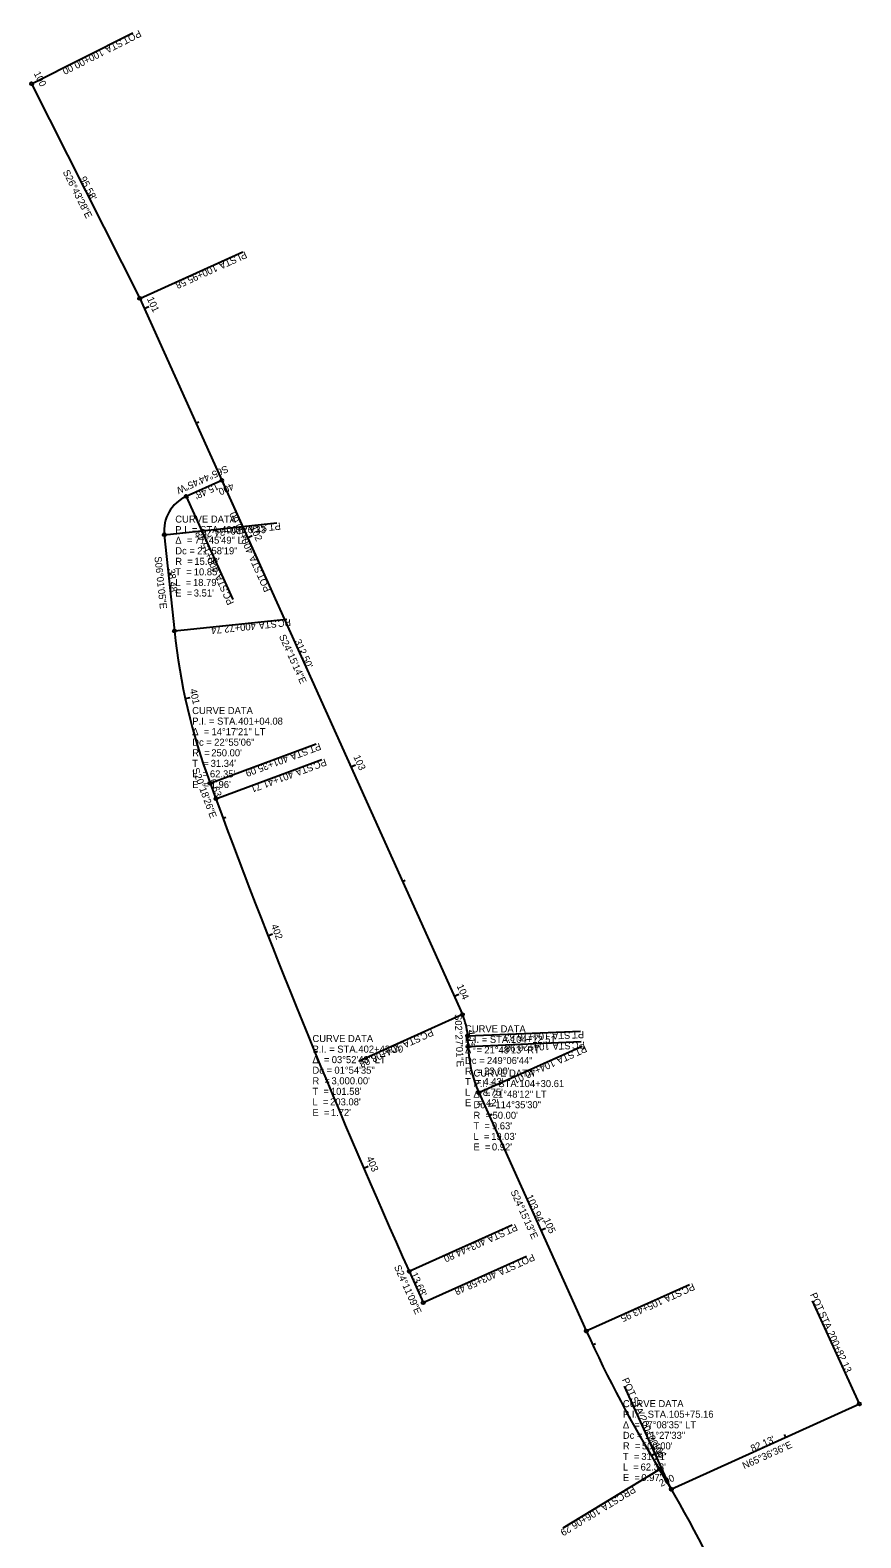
# Model space of a CAD drawing. Extents: x 1584180 to 1585753, y 271314 to 274821.
# Drawn here: x 1584180 to 1584511, y 274221 to 274821 of the extents above; entities that cross this region are included whole.
import ezdxf

# ---------------------------------------------------------------- set-up
doc = ezdxf.new("R2010")
doc.units = 0
for name, color, linetype in [('GE_P_Alignment', 7, 'Continuous'), ('GE_P_Alignment_100_Bearings', 7, 'Continuous'), ('GE_P_Alignment_100_Cardinal_Points', 7, 'Continuous'), ('GE_P_Alignment_100_Curve_Data', 7, 'Continuous'), ('GE_P_Alignment_100_Distances', 7, 'Continuous'), ('GE_P_Alignment_100_Stations', 7, 'Continuous')]:
    doc.layers.add(name, color=color, linetype=linetype)

msp = doc.modelspace()

# ---------------------------------------------------------------- linework, layer by layer
at = {"layer": 'GE_P_Alignment'}
for p, q in [((1584180.89, 274799.28), (1584223.87, 274713.91)), ((1584180.89, 274799.28), (1584223.87, 274713.91)), ((1584223.87, 274713.91), (1584352.24, 274429)), ((1584223.87, 274713.91), (1584352.24, 274429)), ((1584256.5, 274641.5), (1584242.39, 274635.14)), ((1584233.63, 274619.9), (1584237.66, 274581.63)), ((1584251.83, 274521.08), (1584254.13, 274514.86)), ((1584354.25, 274420.53), (1584354.43, 274416.38)), ((1584358.8, 274397.98), (1584401.49, 274303.22)), ((1584331, 274326.93), (1584336.6, 274314.45)), ((1584435.28, 274240.25), (1584510.08, 274274.17))]:
    msp.add_line(p, q, dxfattribs=at)
for centre, radius, start, end in [((1584248.55, 274621.47), 15, 114.25424, 186.01792), ((1584486.29, 274607.84), 250, 186.01792, 200.30709), ((1587067.66, 275556.02), 3000, 200.30709, 204.1857), ((1584331.27, 274419.55), 23, 2.45028, 24.25402), ((1584404.38, 274418.52), 50, 182.45028, 204.25365), ((1584857.36, 274508.6), 500, 204.25365, 211.39671), ((1584003.78, 273987.64), 500, 24.10913, 31.39671)]:
    msp.add_arc(centre, radius, start, end, dxfattribs=at)
at = {"layer": 'GE_P_Alignment_100_Cardinal_Points'}
for p, q in [((1584180.89, 274799.28), (1584221.08, 274819.52)), ((1584223.87, 274713.91), (1584264.9, 274732.4)), ((1584256.5, 274641.5), (1584274.98, 274600.47)), ((1584242.39, 274635.14), (1584260.87, 274594.12)), ((1584233.63, 274619.9), (1584278.38, 274624.61)), ((1584237.66, 274581.63), (1584282.42, 274586.35)), ((1584251.83, 274521.08), (1584294.03, 274536.7)), ((1584254.13, 274514.86), (1584296.33, 274530.48)), ((1584352.24, 274429), (1584311.21, 274410.51)), ((1584354.25, 274420.53), (1584399.21, 274422.46)), ((1584354.43, 274416.38), (1584399.39, 274418.31)), ((1584358.8, 274397.98), (1584399.82, 274416.47)), ((1584331, 274326.93), (1584372.05, 274345.37)), ((1584336.6, 274314.45), (1584377.65, 274332.89)), ((1584401.49, 274303.22), (1584442.52, 274321.7)), ((1584510.08, 274274.17), (1584491.5, 274315.15)), ((1584435.28, 274240.25), (1584416.69, 274281.24)), ((1584430.57, 274248.12), (1584392.16, 274224.68))]:
    msp.add_line(p, q, dxfattribs=at)
for centre in [(1584180.89, 274799.28), (1584223.87, 274713.91), (1584256.5, 274641.5), (1584242.39, 274635.14), (1584233.63, 274619.9), (1584237.66, 274581.63), (1584251.83, 274521.08), (1584254.13, 274514.86), (1584352.24, 274429), (1584354.25, 274420.53), (1584354.43, 274416.38), (1584358.8, 274397.98), (1584331, 274326.93), (1584336.6, 274314.45), (1584401.49, 274303.22), (1584510.08, 274274.17), (1584430.57, 274248.12), (1584435.28, 274240.25)]:
    msp.add_circle(centre, 0.6, dxfattribs=at)
at = {"layer": 'GE_P_Alignment_100_Stations'}
for p, q in [((1584180.89, 274799.28), (1584182.68, 274800.18)), ((1584203.37, 274754.62), (1584204.45, 274755.16)), ((1584225.69, 274709.88), (1584227.51, 274710.7)), ((1584246.23, 274664.3), (1584247.32, 274664.79)), ((1584256.5, 274641.5), (1584257.32, 274639.68)), ((1584266.77, 274618.71), (1584268.59, 274619.53)), ((1584235.28, 274604.25), (1584236.47, 274604.37)), ((1584287.31, 274573.12), (1584288.4, 274573.62)), ((1584241.99, 274554.73), (1584243.95, 274555.16)), ((1584307.84, 274527.54), (1584309.67, 274528.36)), ((1584257.01, 274507.1), (1584258.14, 274507.52)), ((1584328.38, 274481.95), (1584329.48, 274482.44)), ((1584274.88, 274460.4), (1584276.74, 274461.13)), ((1584348.92, 274436.36), (1584350.75, 274437.18)), ((1584293.53, 274414.01), (1584294.64, 274414.47)), ((1584362.9, 274388.87), (1584363.99, 274389.37)), ((1584312.95, 274367.94), (1584314.78, 274368.73)), ((1584383.44, 274343.29), (1584385.26, 274344.11)), ((1584333.13, 274322.19), (1584334.22, 274322.68)), ((1584404.01, 274297.72), (1584405.1, 274298.22)), ((1584480.81, 274260.9), (1584480.32, 274261.99)), ((1584427.33, 274253.51), (1584429.05, 274254.53)), ((1584435.28, 274240.25), (1584434.45, 274242.07))]:
    msp.add_line(p, q, dxfattribs=at)

# ---------------------------------------------------------------- texts
at = {"layer": 'GE_P_Alignment_100_Bearings'}
for s, rotation, p in [('S26°43\'28"E', 296.72445, (1584193.17, 274764.21)), ('S65°44\'45"W', 204.25424, (1584258.31, 274647.58)), ('S06°01\'05"E', 276.01792, (1584229.73, 274611.14)), ('S24°15\'14"E', 294.25402, (1584279.19, 274579.46)), ('S20°18\'26"E', 290.30709, (1584244.68, 274526.56)), ('S02°27\'01"E', 272.45028, (1584349.08, 274429.18)), ('S24°15\'13"E', 294.25365, (1584371.27, 274358.6)), ('S24°11\'09"E', 294.1857, (1584324.94, 274328.7)), ('N65°36\'36"E', 24.39003, (1584464.31, 274248.15))]:
    msp.add_text(s, height=2.8, rotation=rotation, dxfattribs=at).set_placement(p)
at = {"layer": 'GE_P_Alignment_100_Cardinal_Points'}
for s, rotation, p in [('POT', 206.72445, (1584223.6, 274820.74)), ('100+00.00', 206.72445, (1584208.73, 274813.25)), (' STA. ', 206.72445, (1584217.17, 274817.5)), (' STA. ', 204.25402, (1584262.63, 274731.33)), ('PI', 204.25402, (1584265.72, 274732.72)), ('100+95.58', 204.25402, (1584254.01, 274727.45)), ('400+00.00', 114.25424, (1584269.25, 274613.09)), ('400+15.48', 114.25424, (1584255.67, 274605.55)), ('400+34.26', 186.01792, (1584266.01, 274623.27)), (' STA. ', 186.01792, (1584275.41, 274624.26)), ('PT', 186.01792, (1584279.8, 274624.72)), (' STA. ', 114.25424, (1584273.14, 274604.47)), (' STA. ', 114.25424, (1584259.56, 274596.93)), ('POT', 114.25424, (1584276.09, 274597.9)), ('PC', 114.25424, (1584261.44, 274592.75)), ('400+72.74', 186.01792, (1584269.87, 274584.99)), (' STA. ', 186.01792, (1584279.27, 274585.98)), ('PC', 186.01792, (1584283.83, 274586.46)), ('PT', 200.30709, (1584295.34, 274537.14)), ('401+35.09', 200.30709, (1584282.33, 274532.32)), (' STA. ', 200.30709, (1584291.2, 274535.6)), ('PC', 200.30709, (1584297.56, 274530.89)), ('401+41.71', 200.30709, (1584284.39, 274526.02)), (' STA. ', 200.30709, (1584293.26, 274529.3)), ('PC', 204.25402, (1584339.93, 274423.4)), ('104+08.08', 204.25402, (1584327.13, 274417.64)), (' STA. ', 204.25402, (1584335.75, 274421.52)), ('104+16.83', 182.45028, (1584386.69, 274421.88)), ('104+20.98', 182.45028, (1584386.84, 274417.73)), (' STA. ', 182.45028, (1584396.13, 274422.28)), (' STA. ', 182.45028, (1584396.29, 274418.13)), ('PC', 182.45028, (1584400.87, 274418.33)), ('PT', 182.45028, (1584400.54, 274422.47)), ('PT', 204.25365, (1584400.94, 274416.93)), ('104+40.01', 204.25365, (1584388.3, 274411.23)), (' STA. ', 204.25365, (1584396.92, 274415.11)), ('PT', 204.1857, (1584373.35, 274345.91)), ('403+44.80', 204.1857, (1584360.7, 274340.23)), (' STA. ', 204.1857, (1584369.32, 274344.1)), ('POT', 204.1857, (1584380.21, 274333.99)), ('403+58.48', 204.1857, (1584365.02, 274327.17)), (' STA. ', 204.1857, (1584373.64, 274331.04)), ('PC', 204.25365, (1584443.86, 274322.26)), ('105+43.95', 204.25365, (1584431.06, 274316.49)), (' STA. ', 204.25365, (1584439.68, 274320.37)), ('POT', 294.39003, (1584490.41, 274317.65)), (' STA. ', 294.39003, (1584493.38, 274311.09)), ('200+82.13', 294.39003, (1584497.29, 274302.48)), ('POT', 294.39003, (1584415.58, 274283.8)), (' STA. ', 294.39003, (1584418.55, 274277.24)), ('200+00.00', 294.39003, (1584422.45, 274268.64)), (' STA. ', 211.39671, (1584414.12, 274238.03)), ('PRC', 211.39671, (1584420.04, 274241.65)), ('106+06.29', 211.39671, (1584406.05, 274233.11))]:
    msp.add_text(s, height=2.8, rotation=rotation, dxfattribs=at).set_placement(p)
at = {"layer": 'GE_P_Alignment_100_Curve_Data'}
for s, p in [('CURVE DATA', (1584238.01, 274624.72)), ('P.I. = STA. ', (1584238.01, 274620.52)), ('400+26.33', (1584256.28, 274620.52)), ('Δ  = ', (1584238.01, 274616.32)), ('Dc = ', (1584238.01, 274612.12)), ('71°45\'49" LT', (1584245.69, 274616.32)), ('21°58\'19"', (1584246.75, 274612.12)), ('R  = ', (1584238.01, 274607.92)), ("15.00'", (1584245.59, 274607.92)), ('T  = ', (1584238.01, 274603.72)), ("10.85'", (1584245.35, 274603.72)), ('L  = ', (1584238.01, 274599.52)), ('E  = ', (1584238.01, 274595.32)), ("18.79'", (1584245.05, 274599.52)), ("3.51'", (1584245.35, 274595.32)), ('CURVE DATA', (1584244.74, 274548.56)), ('Δ  = ', (1584244.74, 274540.16)), ('P.I. = STA. ', (1584244.74, 274544.36)), ('14°17\'21" LT', (1584252.42, 274540.16)), ('401+04.08', (1584263.01, 274544.36)), ('Dc = ', (1584244.74, 274535.96)), ('22°55\'06"', (1584253.48, 274535.96)), ('R  = ', (1584244.74, 274531.76)), ("250.00'", (1584252.33, 274531.76)), ('T  = ', (1584244.74, 274527.56)), ('L  = ', (1584244.74, 274523.36)), ("62.35'", (1584251.79, 274523.36)), ("31.34'", (1584252.08, 274527.56)), ('E  = ', (1584244.74, 274519.16)), ("1.96'", (1584252.09, 274519.16)), ('CURVE DATA', (1584353.25, 274421.96)), ('CURVE DATA', (1584292.56, 274418.1)), ('P.I. = STA. ', (1584292.56, 274413.9)), ('402+43.30', (1584310.83, 274413.9)), ('P.I. = STA. ', (1584353.25, 274417.76)), ('104+12.51', (1584371.51, 274417.76)), ('Δ  = ', (1584292.56, 274409.7)), ('03°52\'43" LT', (1584300.24, 274409.7)), ('Δ  = ', (1584353.25, 274413.56)), ('Dc = ', (1584353.25, 274409.36)), ('21°48\'13" RT', (1584360.92, 274413.56)), ('249°06\'44"', (1584361.98, 274409.36)), ('Dc = ', (1584292.56, 274405.5)), ('01°54\'35"', (1584301.3, 274405.5)), ('R  = ', (1584353.25, 274405.16)), ('CURVE DATA', (1584356.61, 274404.38)), ("23.00'", (1584360.83, 274405.16)), ('T  = ', (1584292.56, 274397.1)), ('R  = ', (1584292.56, 274401.3)), ("101.58'", (1584299.9, 274397.1)), ("3,000.00'", (1584300.14, 274401.3)), ('T  = ', (1584353.25, 274400.96)), ('L  = ', (1584353.25, 274396.76)), ('Δ  = ', (1584356.61, 274395.98)), ('P.I. = STA. ', (1584356.61, 274400.18)), ("8.75'", (1584360.29, 274396.76)), ("4.43'", (1584360.58, 274400.96)), ('21°48\'12" LT', (1584364.29, 274395.98)), ('104+30.61', (1584374.88, 274400.18)), ('L  = ', (1584292.56, 274392.9)), ("203.08'", (1584299.6, 274392.9)), ('E  = ', (1584353.25, 274392.56)), ('Dc = ', (1584356.61, 274391.78)), (".42'", (1584360.59, 274392.56)), ('114°35\'30"', (1584365.35, 274391.78)), ('E  = ', (1584292.56, 274388.7)), ("1.72'", (1584299.9, 274388.7)), ('R  = ', (1584356.61, 274387.58)), ("50.00'", (1584364.19, 274387.58)), ('T  = ', (1584356.61, 274383.38)), ('L  = ', (1584356.61, 274379.18)), ("19.03'", (1584363.65, 274379.18)), ("9.63'", (1584363.95, 274383.38)), ('E  = ', (1584356.61, 274374.98)), ("0.92'", (1584363.95, 274374.98)), ('CURVE DATA', (1584416.03, 274272.87)), ('Δ  = ', (1584416.03, 274264.47)), ('P.I. = STA. ', (1584416.03, 274268.67)), ('07°08\'35" LT', (1584423.71, 274264.47)), ('105+75.16', (1584434.3, 274268.67)), ('Dc = ', (1584416.03, 274260.27)), ('11°27\'33"', (1584424.77, 274260.27)), ('T  = ', (1584416.03, 274251.87)), ('R  = ', (1584416.03, 274256.07)), ("31.21'", (1584423.37, 274251.87)), ("500.00'", (1584423.61, 274256.07)), ('L  = ', (1584416.03, 274247.67)), ("62.33'", (1584423.07, 274247.67)), ('E  = ', (1584416.03, 274243.47)), ("0.97'", (1584423.37, 274243.47))]:
    msp.add_text(s, height=2.8, dxfattribs=at).set_placement(p)
at = {"layer": 'GE_P_Alignment_100_Distances'}
for s, rotation, p in [("95.58'", 296.72445, (1584199.92, 274761.58)), ("15.48'", 204.25424, (1584254.53, 274640.57)), ("38.48'", 276.01792, (1584235.11, 274606.3)), ("312.50'", 294.25402, (1584285.35, 274577.56)), ("6.63'", 290.30709, (1584251.47, 274522.16)), ("4.15'", 272.45028, (1584354.19, 274422.9)), ("103.94'", 294.25365, (1584377.44, 274356.71)), ("13.68'", 294.1857, (1584331.56, 274325.78)), ("82.13'", 24.39003, (1584467.59, 274254.95))]:
    msp.add_text(s, height=2.8, rotation=rotation, dxfattribs=at).set_placement(p)
at = {"layer": 'GE_P_Alignment_100_Stations'}
for s, rotation, p in [('100', 296.72445, (1584181.62, 274803.4)), ('101', 294.25402, (1584226.67, 274713.78)), ('400', 204.25424, (1584260.57, 274640.6)), ('102', 294.25402, (1584267.7, 274622.73)), ('401', 282.26565, (1584243.77, 274558.34)), ('103', 294.25402, (1584308.78, 274531.55)), ('402', 291.42025, (1584276.01, 274464.37)), ('104', 294.25402, (1584349.86, 274440.37)), ('403', 293.33011, (1584313.95, 274371.93)), ('105', 294.25365, (1584384.36, 274347.33)), ('106', 300.67645, (1584427.77, 274257.67)), ('200', 24.39003, (1584431.2, 274241.15))]:
    msp.add_text(s, height=2.8, rotation=rotation, dxfattribs=at).set_placement(p)

doc.saveas('drawing.dxf')
